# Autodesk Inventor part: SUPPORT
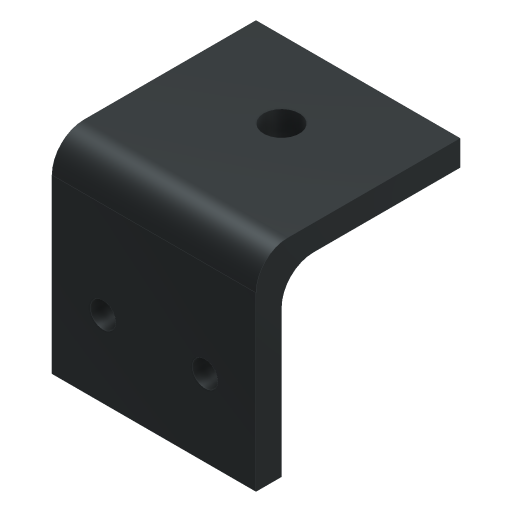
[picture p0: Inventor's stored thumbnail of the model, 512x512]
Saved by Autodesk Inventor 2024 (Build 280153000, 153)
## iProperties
Created: 2016-05
Part Number: SUPPORT
Material: Iron, Cast
Document SubType Name: Modeling
Designer: CADCIM
Density: 7.15 g/cm^3
Appearance: Iron Gray
Mass: 104.47 g
Surface Area: 70.4692 cm^2
Volume: 14.6112 cm^3
Author: CADCIM
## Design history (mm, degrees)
sketch "Sketch1"
  geometry: L1 (0, 0)-(40, 0); L2 (40, 0)-(40, -5); L3 (40, -5)-(5, -5); L4 (5, -5)-(5, -40); L5 (5, -40)-(0, -40); L6 (0, -40)-(0, 0)
  constraints: 12 end point, 2 parallel, 2 perpendicular, 1 horizontal
  dimensions: "d2" = 40 distance between parallel lines of L6 L2; "d3" = 40 distance of L5.end L1.start; "d4" = 5 distance between parallel lines of L1 L3
extrude "Extrusion1" new body sketch "Sketch1" distance "d0" = 40; taper "d1" = 0 deg
sketch "Sketch2"
  geometry: L1 (0, 0)-(0, 35) reference; L2 (0, 35)-(-40, 35) reference; C1 r 3.5 at (-20, 20); 1 further point
  constraints: 1 centre point
  dimensions: "d5" = 7 diameter of C1; "d6" = 20 distance from line of C1.centre L1; "d7" = 15 distance from line of L2 C1.centre
extrude "Extrusion2" cut sketch "Sketch2" distance "d8" = 40; taper "d9" = 0 deg
sketch "Sketch3"
  geometry: L1 (40, 35)-(40, 0) reference; L2 (0, 35)-(40, 35) reference; C1 r 2.5 at (10, 20); C2 r 2.5 at (30, 20); 1 further point
  constraints: 2 centre point, 1 equal radius, 1 horizontal alignment
  dimensions: "d10" = 20 distance of C2.centre C1.centre; "d11" = 10 distance from line of L1 C2.centre; "d12" = 15 distance from line of L2 C2.centre; "d13" = 5 diameter of C1
extrude "Extrusion3" cut sketch "Sketch3" distance "d14" = 40; taper "d15" = 0 deg
fillet "Fillet1" dims "d16" = 6.25
body "Solid1"
